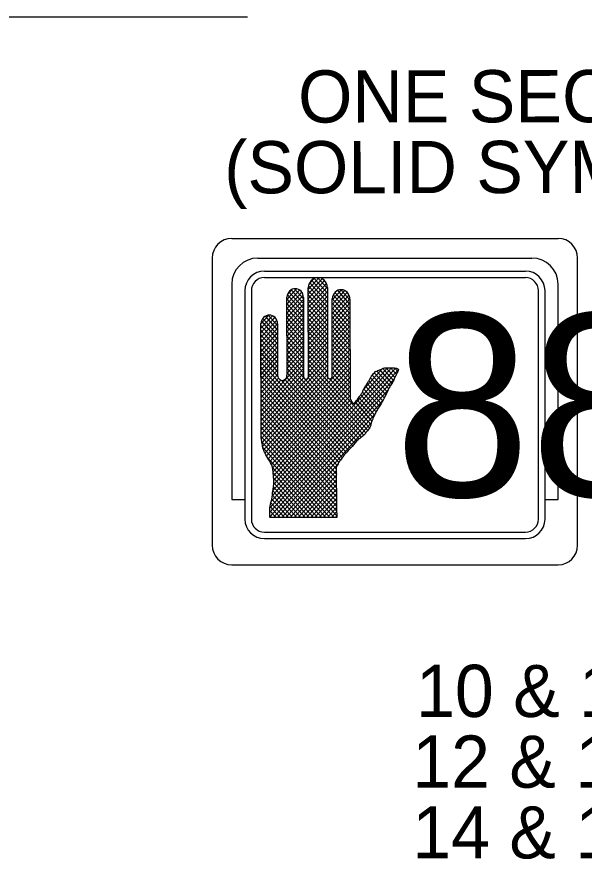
# Model space of a CAD drawing. Extents: x 1280123 to 1281123, y 1892664 to 1893304.
# Drawn here: x 1280389.4 to 1280432.9, y 1892814.8 to 1892879.3 of the extents above; entities that cross this region are included whole.
import ezdxf

# ---------------------------------------------------------------- set-up
doc = ezdxf.new("R2010")
doc.units = 0
doc.layers.add('T_Drafting', color=7, linetype='Continuous')
doc.layers.add('T_Notes', color=7, linetype='Continuous')

msp = doc.modelspace()

# ---------------------------------------------------------------- linework, layer by layer
at = {"layer": 'T_Drafting'}
for p, q in [((1280405.884, 1892862.359), (1280430.884, 1892862.359)), ((1280404.384, 1892860.859), (1280404.384, 1892838.859)), ((1280407.884, 1892860.859), (1280428.884, 1892860.859)), ((1280432.384, 1892838.859), (1280432.384, 1892860.859)), ((1280408.384, 1892859.859), (1280428.384, 1892859.859)), ((1280405.884, 1892858.859), (1280405.884, 1892842.359)), ((1280408.384, 1892859.359), (1280428.384, 1892859.359)), ((1280411.748, 1892858.443), (1280412.57, 1892859.357)), ((1280411.748, 1892858.09), (1280412.813, 1892859.274)), ((1280411.748, 1892857.737), (1280412.997, 1892859.125)), ((1280411.749, 1892857.384), (1280413.132, 1892858.92)), ((1280411.801, 1892858.856), (1280412.202, 1892859.302)), ((1280411.853, 1892858.971), (1280413.212, 1892857.461)), ((1280411.999, 1892859.163), (1280413.212, 1892857.815)), ((1280412.195, 1892859.299), (1280413.211, 1892858.169)), ((1280412.456, 1892859.362), (1280413.211, 1892858.523)), ((1280412.922, 1892859.197), (1280413.064, 1892859.04)), ((1280430.884, 1892842.359), (1280430.884, 1892858.859)), ((1280406.884, 1892858.359), (1280406.884, 1892840.859)), ((1280407.384, 1892858.359), (1280407.384, 1892840.859)), ((1280410.109, 1892857.684), (1280410.847, 1892858.503)), ((1280410.11, 1892857.331), (1280411.079, 1892858.407)), ((1280410.11, 1892856.978), (1280411.247, 1892858.241)), ((1280410.167, 1892858.101), (1280410.478, 1892858.446)), ((1280410.262, 1892858.265), (1280411.383, 1892857.018)), ((1280410.437, 1892858.423), (1280411.383, 1892857.372)), ((1280410.679, 1892858.508), (1280411.383, 1892857.726)), ((1280411.104, 1892858.389), (1280411.273, 1892858.202)), ((1280411.755, 1892851.759), (1280411.747, 1892858.586)), ((1280411.748, 1892858.381), (1280413.213, 1892856.753)), ((1280411.749, 1892857.031), (1280413.207, 1892858.65)), ((1280411.75, 1892856.678), (1280413.211, 1892858.302)), ((1280411.763, 1892858.718), (1280413.213, 1892857.107)), ((1280413.211, 1892858.605), (1280413.218, 1892851.827)), ((1280413.578, 1892857.648), (1280414.284, 1892858.432)), ((1280413.578, 1892857.295), (1280414.541, 1892858.365)), ((1280413.579, 1892856.942), (1280414.73, 1892858.221)), ((1280413.793, 1892858.23), (1280414.94, 1892856.956)), ((1280413.985, 1892858.37), (1280414.939, 1892857.31)), ((1280414.247, 1892858.433), (1280414.939, 1892857.664)), ((1280429.384, 1892840.859), (1280429.384, 1892858.359)), ((1280429.884, 1892840.859), (1280429.884, 1892858.359)), ((1280410.116, 1892851.886), (1280410.109, 1892857.851)), ((1280410.109, 1892857.727), (1280411.384, 1892856.31)), ((1280410.111, 1892856.624), (1280411.356, 1892858.008)), ((1280410.111, 1892856.271), (1280411.383, 1892857.684)), ((1280410.145, 1892858.041), (1280411.384, 1892856.664)), ((1280411.382, 1892857.837), (1280411.389, 1892851.791)), ((1280411.748, 1892858.027), (1280413.213, 1892856.399)), ((1280411.749, 1892857.673), (1280413.214, 1892856.045)), ((1280411.75, 1892856.325), (1280413.212, 1892857.949)), ((1280411.75, 1892855.972), (1280413.212, 1892857.596)), ((1280413.585, 1892851.794), (1280413.578, 1892857.742)), ((1280413.579, 1892856.589), (1280414.865, 1892858.018)), ((1280413.579, 1892857.76), (1280414.94, 1892856.248)), ((1280413.58, 1892856.236), (1280414.936, 1892857.744)), ((1280413.655, 1892858.03), (1280414.94, 1892856.602)), ((1280414.939, 1892857.695), (1280414.948, 1892850.038)), ((1280410.11, 1892857.373), (1280411.385, 1892855.956)), ((1280410.11, 1892857.019), (1280411.385, 1892855.602)), ((1280410.111, 1892855.918), (1280411.383, 1892857.331)), ((1280410.112, 1892855.565), (1280411.383, 1892856.978)), ((1280411.749, 1892857.319), (1280413.214, 1892855.691)), ((1280411.749, 1892856.965), (1280413.215, 1892855.337)), ((1280411.751, 1892855.618), (1280413.212, 1892857.242)), ((1280411.751, 1892855.265), (1280413.213, 1892856.889)), ((1280413.578, 1892857.408), (1280414.941, 1892855.894)), ((1280413.579, 1892857.054), (1280414.941, 1892855.54)), ((1280413.58, 1892855.883), (1280414.939, 1892857.393)), ((1280413.58, 1892855.53), (1280414.94, 1892857.04)), ((1280408.121, 1892855.828), (1280408.717, 1892856.49)), ((1280408.122, 1892855.475), (1280408.992, 1892856.442)), ((1280408.122, 1892855.122), (1280409.188, 1892856.306)), ((1280408.268, 1892856.237), (1280409.395, 1892854.984)), ((1280408.441, 1892856.398), (1280409.395, 1892855.338)), ((1280408.68, 1892856.486), (1280409.395, 1892855.692)), ((1280409.083, 1892856.392), (1280409.306, 1892856.145)), ((1280410.111, 1892856.665), (1280411.385, 1892855.248)), ((1280410.111, 1892856.311), (1280411.386, 1892854.894)), ((1280410.112, 1892855.212), (1280411.384, 1892856.625)), ((1280410.113, 1892854.859), (1280411.384, 1892856.272)), ((1280411.75, 1892856.611), (1280413.215, 1892854.983)), ((1280411.75, 1892856.257), (1280413.215, 1892854.629)), ((1280411.752, 1892854.912), (1280413.213, 1892856.536)), ((1280413.579, 1892856.7), (1280414.941, 1892855.186)), ((1280413.579, 1892856.346), (1280414.942, 1892854.832)), ((1280413.581, 1892855.177), (1280414.94, 1892856.687)), ((1280413.581, 1892854.824), (1280414.94, 1892856.334)), ((1280408.13, 1892847.588), (1280408.121, 1892855.831)), ((1280408.121, 1892855.693), (1280409.396, 1892854.276)), ((1280408.122, 1892854.769), (1280409.325, 1892856.105)), ((1280408.123, 1892854.416), (1280409.394, 1892855.828)), ((1280408.154, 1892856.011), (1280409.396, 1892854.63)), ((1280409.394, 1892855.816), (1280409.399, 1892851.885)), ((1280410.111, 1892855.957), (1280411.386, 1892854.54)), ((1280410.112, 1892855.603), (1280411.387, 1892854.186)), ((1280410.113, 1892854.506), (1280411.385, 1892855.919)), ((1280411.751, 1892855.903), (1280413.216, 1892854.275)), ((1280411.752, 1892854.559), (1280413.214, 1892856.183)), ((1280411.752, 1892854.206), (1280413.214, 1892855.83)), ((1280413.58, 1892855.992), (1280414.942, 1892854.478)), ((1280413.58, 1892855.638), (1280414.943, 1892854.124)), ((1280413.582, 1892854.47), (1280414.941, 1892855.981)), ((1280413.582, 1892854.117), (1280414.941, 1892855.627)), ((1280408.122, 1892855.339), (1280409.397, 1892853.922)), ((1280408.122, 1892854.985), (1280409.397, 1892853.568)), ((1280408.123, 1892854.063), (1280409.395, 1892855.476)), ((1280408.124, 1892853.709), (1280409.395, 1892855.122)), ((1280410.112, 1892855.249), (1280411.387, 1892853.832)), ((1280410.113, 1892854.153), (1280411.385, 1892855.566)), ((1280410.114, 1892853.8), (1280411.385, 1892855.212)), ((1280411.751, 1892855.549), (1280413.216, 1892853.921)), ((1280411.751, 1892855.195), (1280413.217, 1892853.567)), ((1280411.753, 1892853.853), (1280413.214, 1892855.477)), ((1280411.753, 1892853.5), (1280413.215, 1892855.124)), ((1280413.581, 1892855.284), (1280414.943, 1892853.77)), ((1280413.582, 1892853.764), (1280414.941, 1892855.274)), ((1280408.123, 1892854.631), (1280409.397, 1892853.214)), ((1280408.124, 1892853.356), (1280409.396, 1892854.769)), ((1280408.124, 1892853.003), (1280409.396, 1892854.416)), ((1280410.113, 1892854.895), (1280411.387, 1892853.478)), ((1280410.113, 1892854.541), (1280411.388, 1892853.124)), ((1280410.114, 1892853.446), (1280411.386, 1892854.859)), ((1280410.115, 1892853.093), (1280411.386, 1892854.506)), ((1280411.752, 1892854.841), (1280413.217, 1892853.213)), ((1280411.752, 1892854.487), (1280413.217, 1892852.859)), ((1280411.754, 1892853.147), (1280413.215, 1892854.771)), ((1280411.754, 1892852.794), (1280413.216, 1892854.417)), ((1280413.581, 1892854.93), (1280414.943, 1892853.416)), ((1280413.581, 1892854.576), (1280414.944, 1892853.062)), ((1280413.583, 1892853.411), (1280414.942, 1892854.921)), ((1280413.583, 1892853.058), (1280414.942, 1892854.568)), ((1280408.123, 1892854.277), (1280409.398, 1892852.86)), ((1280408.123, 1892853.923), (1280409.398, 1892852.506)), ((1280408.125, 1892852.65), (1280409.396, 1892854.063)), ((1280408.125, 1892852.297), (1280409.397, 1892853.71)), ((1280410.113, 1892854.187), (1280411.388, 1892852.77)), ((1280410.114, 1892853.833), (1280411.389, 1892852.416)), ((1280410.115, 1892852.74), (1280411.387, 1892854.153)), ((1280410.115, 1892852.387), (1280411.387, 1892853.8)), ((1280411.753, 1892854.133), (1280413.218, 1892852.505)), ((1280411.753, 1892853.779), (1280413.218, 1892852.151)), ((1280411.754, 1892852.44), (1280413.216, 1892854.064)), ((1280411.755, 1892852.087), (1280413.216, 1892853.711)), ((1280413.582, 1892854.222), (1280414.944, 1892852.708)), ((1280413.582, 1892853.868), (1280414.944, 1892852.355)), ((1280413.584, 1892852.705), (1280414.942, 1892854.215)), ((1280413.584, 1892852.352), (1280414.943, 1892853.862)), ((1280408.124, 1892853.569), (1280409.399, 1892852.152)), ((1280408.124, 1892853.215), (1280409.411, 1892851.786)), ((1280408.125, 1892851.944), (1280409.397, 1892853.357)), ((1280408.128, 1892849.472), (1280411.388, 1892853.094)), ((1280408.423, 1892845.91), (1280414.944, 1892853.155)), ((1280410.114, 1892853.479), (1280411.389, 1892852.062)), ((1280410.115, 1892853.125), (1280411.405, 1892851.691)), ((1280410.116, 1892852.034), (1280411.387, 1892853.447)), ((1280411.751, 1892851.73), (1280413.217, 1892853.358)), ((1280411.753, 1892853.425), (1280413.213, 1892851.803)), ((1280411.754, 1892853.071), (1280416.448, 1892847.856)), ((1280413.583, 1892853.514), (1280414.945, 1892852.001)), ((1280413.583, 1892853.16), (1280414.945, 1892851.647)), ((1280413.584, 1892851.999), (1280414.943, 1892853.509)), ((1280408.124, 1892852.861), (1280414.502, 1892845.775)), ((1280408.125, 1892852.507), (1280414.354, 1892845.586)), ((1280408.126, 1892851.591), (1280409.398, 1892853.004)), ((1280408.126, 1892851.237), (1280409.398, 1892852.651)), ((1280408.129, 1892849.119), (1280411.388, 1892852.741)), ((1280408.129, 1892848.766), (1280411.389, 1892852.388)), ((1280408.142, 1892847.366), (1280413.217, 1892853.005)), ((1280408.154, 1892847.025), (1280413.218, 1892852.652)), ((1280408.546, 1892845.694), (1280414.944, 1892852.802)), ((1280408.672, 1892845.479), (1280414.944, 1892852.449)), ((1280408.816, 1892841.751), (1280418.421, 1892852.424)), ((1280408.921, 1892842.221), (1280418.133, 1892852.456)), ((1280408.992, 1892842.653), (1280417.814, 1892852.456)), ((1280410.115, 1892852.771), (1280415.462, 1892846.83)), ((1280410.115, 1892852.417), (1280415.305, 1892846.651)), ((1280411.754, 1892852.717), (1280416.308, 1892847.657)), ((1280411.755, 1892852.363), (1280416.158, 1892847.471)), ((1280413.583, 1892852.806), (1280414.945, 1892851.293)), ((1280413.584, 1892852.452), (1280414.946, 1892850.939)), ((1280415.985, 1892850.778), (1280417.441, 1892852.395)), ((1280417.45, 1892852.399), (1280418.281, 1892851.475)), ((1280417.717, 1892852.456), (1280418.383, 1892851.716)), ((1280418.035, 1892852.456), (1280418.496, 1892851.944)), ((1280418.377, 1892852.43), (1280418.607, 1892852.174)), ((1280408.125, 1892852.153), (1280414.22, 1892845.381)), ((1280408.126, 1892851.799), (1280414.077, 1892845.187)), ((1280408.127, 1892850.884), (1280409.398, 1892852.298)), ((1280408.127, 1892850.531), (1280409.399, 1892851.944)), ((1280408.129, 1892848.412), (1280411.389, 1892852.034)), ((1280408.202, 1892846.726), (1280413.218, 1892852.299)), ((1280408.251, 1892846.427), (1280413.218, 1892851.946)), ((1280408.795, 1892845.263), (1280414.945, 1892852.096)), ((1280408.806, 1892841.386), (1280418.652, 1892852.327)), ((1280408.916, 1892845.044), (1280414.945, 1892851.743)), ((1280410.09, 1892851.738), (1280414.986, 1892846.297)), ((1280410.116, 1892852.063), (1280415.148, 1892846.471)), ((1280411.755, 1892852.009), (1280416.001, 1892847.291)), ((1280413.577, 1892851.752), (1280414.947, 1892850.231)), ((1280413.584, 1892852.098), (1280414.946, 1892850.585)), ((1280416.587, 1892851.799), (1280416.929, 1892852.18)), ((1280416.642, 1892851.882), (1280417.797, 1892850.599)), ((1280416.793, 1892852.068), (1280417.909, 1892850.828)), ((1280416.99, 1892852.203), (1280418.031, 1892851.046)), ((1280417.215, 1892852.307), (1280418.159, 1892851.257)), ((1280408.126, 1892851.445), (1280413.965, 1892844.957)), ((1280408.126, 1892851.091), (1280413.881, 1892844.697)), ((1280408.127, 1892850.178), (1280409.462, 1892851.661)), ((1280408.128, 1892849.825), (1280409.643, 1892851.509)), ((1280408.13, 1892848.059), (1280411.403, 1892851.696)), ((1280408.13, 1892847.706), (1280411.613, 1892851.576)), ((1280408.316, 1892846.145), (1280413.276, 1892851.656)), ((1280408.806, 1892841.033), (1280418.345, 1892851.632)), ((1280409.011, 1892844.796), (1280414.945, 1892851.39)), ((1280409.667, 1892851.501), (1280414.661, 1892845.951)), ((1280409.944, 1892851.546), (1280414.824, 1892846.125)), ((1280411.497, 1892851.589), (1280415.633, 1892846.993)), ((1280411.734, 1892851.679), (1280415.821, 1892847.138)), ((1280413.391, 1892851.605), (1280416.541, 1892848.105)), ((1280416.25, 1892851.257), (1280417.448, 1892849.926)), ((1280416.39, 1892851.456), (1280417.568, 1892850.147)), ((1280416.511, 1892851.675), (1280417.685, 1892850.37)), ((1280408.127, 1892850.737), (1280413.892, 1892844.331)), ((1280409.046, 1892844.481), (1280414.946, 1892851.037)), ((1280409.071, 1892840.974), (1280417.87, 1892850.75)), ((1280409.077, 1892844.162), (1280414.946, 1892850.683)), ((1280415.9, 1892850.585), (1280417.066, 1892849.29)), ((1280416.006, 1892850.821), (1280417.197, 1892849.498)), ((1280416.126, 1892851.041), (1280417.326, 1892849.708)), ((1280408.127, 1892850.383), (1280413.878, 1892843.994)), ((1280408.128, 1892850.029), (1280413.879, 1892843.639)), ((1280409.037, 1892843.057), (1280415.109, 1892849.804)), ((1280409.093, 1892843.473), (1280414.992, 1892850.028)), ((1280409.095, 1892843.829), (1280414.946, 1892850.33)), ((1280409.39, 1892840.974), (1280417.451, 1892849.932)), ((1280415.331, 1892849.804), (1280416.623, 1892848.368)), ((1280415.48, 1892849.992), (1280416.718, 1892848.617)), ((1280415.628, 1892850.181), (1280416.825, 1892848.85)), ((1280415.762, 1892850.386), (1280416.944, 1892849.072)), ((1280408.128, 1892849.675), (1280413.895, 1892843.268)), ((1280408.128, 1892849.321), (1280413.896, 1892842.912)), ((1280408.129, 1892848.967), (1280413.897, 1892842.558)), ((1280408.129, 1892848.613), (1280413.897, 1892842.204)), ((1280409.709, 1892840.975), (1280416.869, 1892848.931)), ((1280408.129, 1892848.259), (1280413.899, 1892841.848)), ((1280408.13, 1892847.905), (1280413.914, 1892841.479)), ((1280410.027, 1892840.975), (1280416.586, 1892848.263)), ((1280408.132, 1892847.549), (1280413.934, 1892841.103)), ((1280408.145, 1892847.182), (1280413.726, 1892840.98)), ((1280408.195, 1892846.773), (1280413.408, 1892840.98)), ((1280408.266, 1892846.339), (1280413.09, 1892840.98)), ((1280408.578, 1892845.64), (1280412.772, 1892840.979)), ((1280409.009, 1892844.808), (1280412.455, 1892840.979)), ((1280410.346, 1892840.976), (1280414.019, 1892845.057)), ((1280409.054, 1892844.403), (1280412.137, 1892840.978)), ((1280409.086, 1892844.014), (1280411.819, 1892840.978)), ((1280410.664, 1892840.976), (1280413.888, 1892844.558)), ((1280410.983, 1892840.977), (1280413.886, 1892844.202)), ((1280409.099, 1892843.647), (1280411.501, 1892840.977)), ((1280411.302, 1892840.977), (1280413.876, 1892843.838)), ((1280411.62, 1892840.978), (1280413.884, 1892843.493)), ((1280408.996, 1892842.7), (1280410.548, 1892840.976)), ((1280409.031, 1892843.015), (1280410.866, 1892840.976)), ((1280409.078, 1892843.317), (1280411.184, 1892840.977)), ((1280411.939, 1892840.978), (1280413.896, 1892843.153)), ((1280412.257, 1892840.978), (1280413.897, 1892842.8)), ((1280405.884, 1892842.359), (1280406.884, 1892842.359)), ((1280408.886, 1892842.115), (1280409.912, 1892840.975)), ((1280408.961, 1892842.386), (1280410.23, 1892840.976)), ((1280412.576, 1892840.979), (1280413.897, 1892842.447)), ((1280412.895, 1892840.979), (1280413.897, 1892842.093)), ((1280429.884, 1892842.359), (1280430.884, 1892842.359)), ((1280408.807, 1892841.496), (1280409.277, 1892840.974)), ((1280408.822, 1892841.834), (1280409.595, 1892840.975)), ((1280413.213, 1892840.98), (1280413.902, 1892841.746)), ((1280413.532, 1892840.98), (1280413.917, 1892841.408)), ((1280408.806, 1892841.144), (1280408.959, 1892840.974)), ((1280408.832, 1892840.974), (1280408.806, 1892841.006)), ((1280413.911, 1892840.981), (1280408.832, 1892840.974)), ((1280413.85, 1892840.981), (1280413.934, 1892841.073)), ((1280413.935, 1892840.975), (1280413.911, 1892840.981)), ((1280408.384, 1892839.859), (1280428.384, 1892839.859)), ((1280408.384, 1892839.359), (1280428.384, 1892839.359)), ((1280405.884, 1892837.359), (1280430.884, 1892837.359))]:
    msp.add_line(p, q, dxfattribs=at)
for centre, radius, start, end in [((1280405.884, 1892860.859), 1.5, 90, 180), ((1280430.884, 1892860.859), 1.5, 0, 90), ((1280407.884, 1892858.859), 2, 90, 180), ((1280428.884, 1892858.859), 2, 0, 90), ((1280408.384, 1892858.359), 1.5, 90, 180), ((1280428.384, 1892858.359), 1.5, 0, 90), ((1280408.384, 1892858.359), 1, 90, 180), ((1280428.384, 1892858.359), 1, 0, 90), ((1280408.384, 1892840.859), 1.5, 180, 270), ((1280408.384, 1892840.859), 1, 180, 270), ((1280428.384, 1892840.859), 1.5, 270, 0), ((1280428.384, 1892840.859), 1, 270, 0), ((1280405.884, 1892838.859), 1.5, 180, 270), ((1280430.884, 1892838.859), 1.5, 270, 0)]:
    msp.add_arc(centre, radius, start, end, dxfattribs=at)
for centre, major_axis, start_param, end_param in [((1280412.48, 1892858.548), (0, -0.814), 1.640121, 4.665593), ((1280410.746, 1892857.803), (0, -0.709), 1.618611, 4.644084), ((1280414.257, 1892857.675), (0, -0.758), 1.597842, 4.623315), ((1280408.757, 1892855.783), (0, -0.709), 1.618611, 4.644084), ((1280409.757, 1892851.886), (0, -0.398), 4.713646, 7.855239), ((1280411.572, 1892851.775), (0, -0.204), 4.633755, 7.775348), ((1280413.399, 1892851.812), (0, -0.207), 4.624552, 7.766145)]:
    msp.add_ellipse(centre, major_axis=major_axis, ratio=0.9, start_param=start_param, end_param=end_param, dxfattribs=at)
for points in [[(1280414.947, 1892850.039), (1280414.998, 1892850.025), (1280415.068, 1892849.87), (1280415.156, 1892849.751), (1280415.208, 1892849.733), (1280415.295, 1892849.752), (1280415.349, 1892849.832), (1280415.507, 1892850.026), (1280415.631, 1892850.184), (1280415.701, 1892850.3), (1280415.771, 1892850.398), (1280415.894, 1892850.574), (1280415.964, 1892850.732), (1280416.069, 1892850.946), (1280416.14, 1892851.064), (1280416.263, 1892851.278), (1280416.402, 1892851.475), (1280416.508, 1892851.67), (1280416.63, 1892851.866), (1280416.737, 1892852.003), (1280416.894, 1892852.16), (1280417.087, 1892852.239), (1280417.193, 1892852.298), (1280417.352, 1892852.356), (1280417.492, 1892852.416), (1280417.704, 1892852.456), (1280417.88, 1892852.456), (1280418.108, 1892852.457), (1280418.32, 1892852.437), (1280418.566, 1892852.398), (1280418.636, 1892852.357), (1280418.652, 1892852.3), (1280418.549, 1892852.046), (1280418.478, 1892851.908), (1280418.409, 1892851.77), (1280418.338, 1892851.615), (1280418.302, 1892851.517), (1280418.162, 1892851.262), (1280417.953, 1892850.91), (1280417.671, 1892850.343), (1280417.32, 1892849.695), (1280417.039, 1892849.245), (1280416.88, 1892848.952), (1280416.741, 1892848.677), (1280416.659, 1892848.46), (1280416.615, 1892848.348), (1280416.458, 1892847.876), (1280416.214, 1892847.543), (1280416.02, 1892847.309), (1280415.739, 1892847.072), (1280415.563, 1892846.935), (1280415.107, 1892846.425), (1280414.703, 1892845.996), (1280414.44, 1892845.701), (1280414.21, 1892845.367), (1280414.096, 1892845.222), (1280414, 1892845.017), (1280413.894, 1892844.82), (1280413.895, 1892844.39), (1280413.878, 1892844.004), (1280413.878, 1892843.65), (1280413.896, 1892843.182), (1280413.897, 1892842.732), (1280413.897, 1892842.008), (1280413.916, 1892841.425), (1280413.933, 1892841.209), (1280413.934, 1892841.051), (1280413.934, 1892840.976)], [(1280408.806, 1892841.006), (1280408.806, 1892841.32), (1280408.822, 1892841.847), (1280408.962, 1892842.395), (1280409.032, 1892843.021), (1280409.084, 1892843.373), (1280409.084, 1892844.058), (1280409.03, 1892844.625), (1280408.977, 1892844.918), (1280408.713, 1892845.406), (1280408.431, 1892845.896), (1280408.272, 1892846.307), (1280408.2, 1892846.737), (1280408.147, 1892847.07), (1280408.147, 1892847.284), (1280408.13, 1892847.588)]]:
    msp.add_spline(points, degree=3, dxfattribs=at)
at = {"layer": 'T_Notes'}
msp.add_line((1280308.906, 1892879.338), (1280407.091, 1892879.338), dxfattribs=at)

# ---------------------------------------------------------------- texts
at = {"layer": 'T_Drafting'}
for s, height, p in [('ONE SECTION', 4, (1280410.969, 1892871.237)), ('(SOLID SYMBOL)', 4, (1280405.304, 1892865.811)), ('88', 14, (1280418.348, 1892842.58))]:
    msp.add_text(s, height=height, rotation=0.07203, dxfattribs=at).set_placement(p)
at = {"layer": 'T_Notes'}
for s, p in [('10 & 11', (1280420.007, 1892825.697)), ('12 & 13', (1280419.715, 1892820.279)), ('14 & 15', (1280419.716, 1892814.861))]:
    msp.add_text(s, height=4, dxfattribs=at).set_placement(p)

doc.saveas('drawing.dxf')
